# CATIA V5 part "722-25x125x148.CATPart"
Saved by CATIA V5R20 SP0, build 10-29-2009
Part number: 722-25x125x148
Definition: NONE
Nomenclature: 722-25x125x148
Source: Unknown
Description: 722-25x125x148
Bounding box of the stored display mesh (mm): x -12.5 to 12.5, y -12.5 to 12.5, z -113 to 35
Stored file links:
  C:\Users\Utente\Desktop\IO LAVORO\3D X SITO CF\X SITO\722\722-25x125x148.CATPart
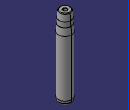
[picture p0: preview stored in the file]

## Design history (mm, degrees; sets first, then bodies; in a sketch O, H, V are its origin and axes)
Body1 "722-25x125x148" (main body)
  Solid1: solid without history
